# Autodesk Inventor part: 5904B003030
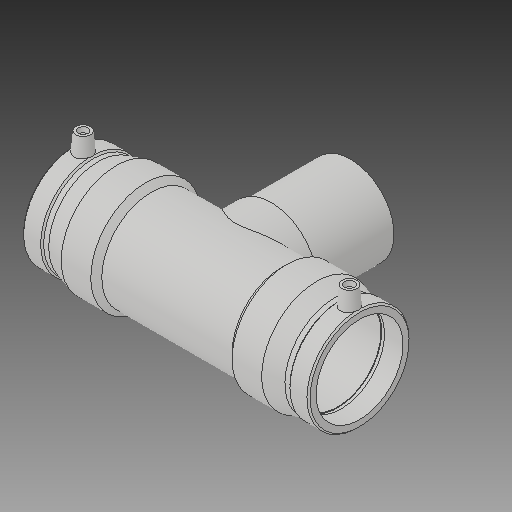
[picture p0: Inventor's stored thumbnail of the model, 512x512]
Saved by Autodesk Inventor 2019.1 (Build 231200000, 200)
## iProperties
Created: 2017-06
Part Number: 5904B003030
Material: Generic
Description: PLASSON TEE 3''IPS
Document SubType Name: Modeling
Designer: KIM
Mass: 17327.5 g
Surface Area: 12195.1 cm^2
Volume: 17327.5 cm^3
Density: 1 g/cm^3
Appearance: Default
Author: KIM
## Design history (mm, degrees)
derived "5904B.ipt"
feature "Solid1::5904B.ipt"
tag "TaggingFeature1"
body "Solid1"
other parameters: "d0" = 292.1, "d1" = 88.7, "d2" = 112.014, "d3" = 70.612, "d4" = 73.025, "d5" = 100.8126, "d6" = 84.265, "d7" = 88.7, "d8" = 168 deg, "d10" = 28.2448, "d11" = 9.41493, "d13" = 292.1, "d14" = 17.6296, "d17" = 79.83, "d18" = 88.7, "d19" = 3.52592, "d20" = 168 deg, "d22" = 104.17302, "d23" = 112.014, "d24" = 101.04783, "d25" = 135 deg, "d26" = 204.47, "d27" = 135 deg, "d29" = 70.104, "d30" = 15, "d31" = 116.84, "d34" = 5 deg, "d35" = 15, "d39" = 5 deg, "d40" = 9.6, "d41" = 4.8, "d42" = 6, "d43" = 0, "d45" = 4, "d46" = 14, "d47" = 0, "d48" = -136.906, "d49" = 88.7, "d51" = 0, "d52" = 70.96, "d54" = 0, "d55" = 100.8126, "d56" = 112.014, "d57" = 102.235, "d58" = 135 deg, "d59" = 70.612, "d60" = 70.612, "d61" = 135 deg, "d62" = 136.906, "d72" = 132.9055, "d73" = 66.45275, "d74" = -136.906, "d75" = 93.135, "d77" = 0, "d78" = 70.96, "d80" = 0, "d81" = 88.7, "d82" = 80.899, "d83" = 0, "d84" = 3, "d85" = 0, "d86" = 3, "d87" = 0, "d88" = 20.47748, "d89" = 5.11937, "d90" = 20.47748, "d_" = 88.7, "L_" = 292.1, "L_1" = 70.612, "D_" = 112.014, "A_" = 70.104, "d_2" = 12, "H_" = 136.906
